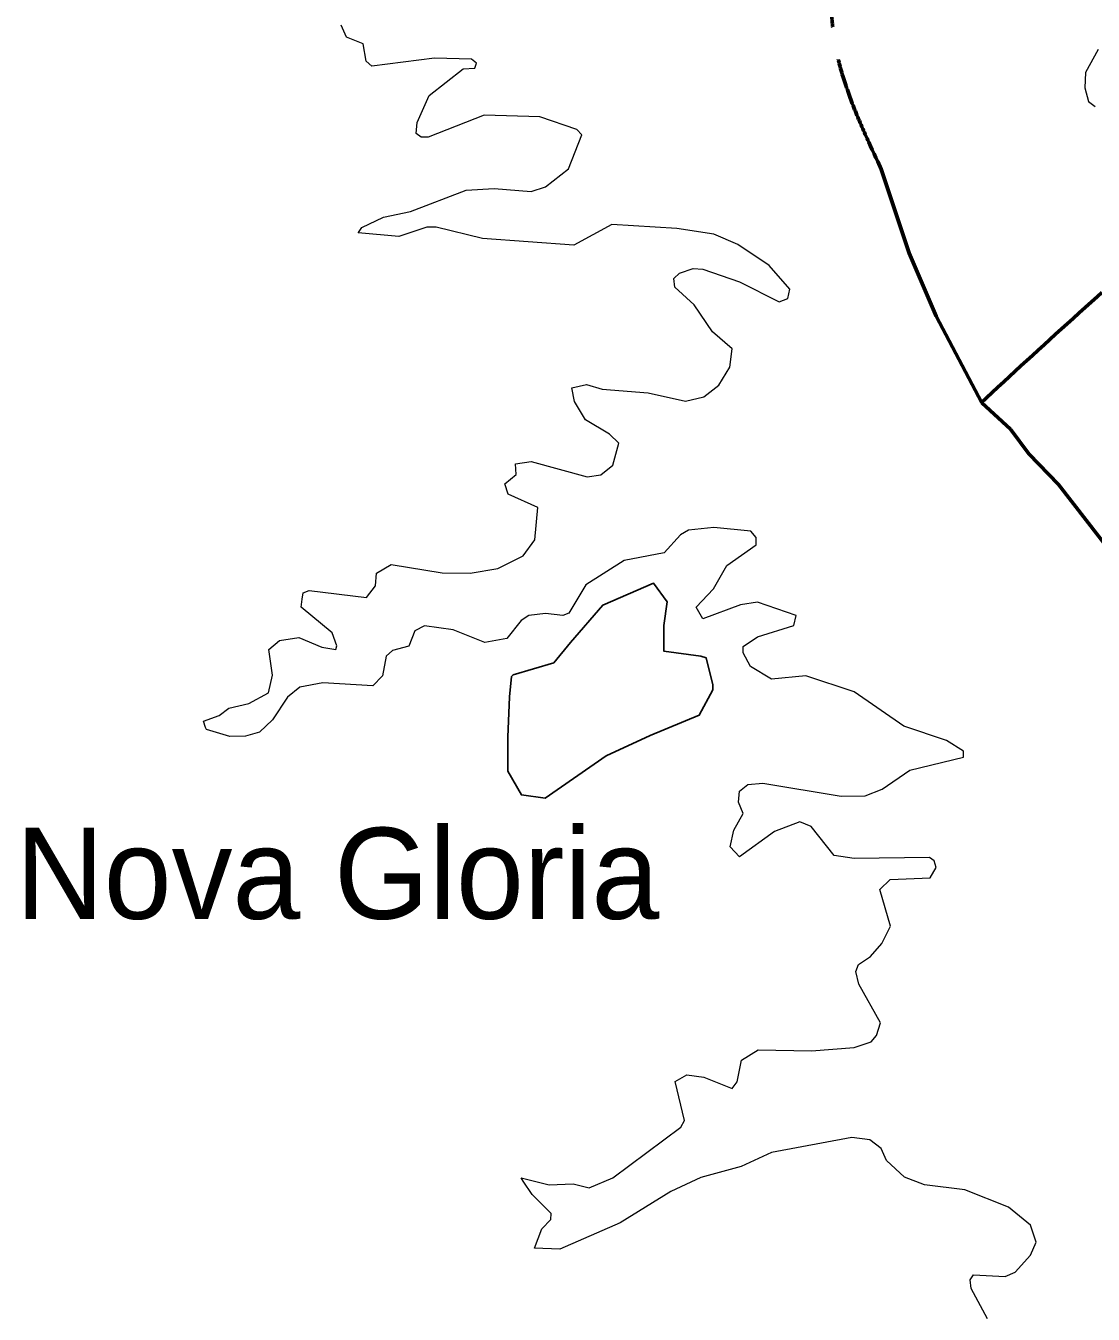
# Model space of a CAD drawing. Extents: x 553962 to 842807, y 8883888 to 9032388.
# Drawn here: x 578481 to 584337, y 8963682 to 8970754 of the extents above; entities that cross this region are included whole.
import ezdxf
from ezdxf.enums import TextEntityAlignment as Align

# ---------------------------------------------------------------- set-up
doc = ezdxf.new("R2010")
doc.units = 0
doc.header["$LTSCALE"] = 150
doc.linetypes.add('LONG_DASH_SHORT_DASH', pattern=[9.9, 6, -1.2, 1.5, -1.2])
for name, color, linetype, lineweight in [('21', 7, 'Continuous', 25), ('25', 7, 'Continuous', 13), ('7', 7, 'LONG_DASH_SHORT_DASH', 60)]:
    doc.layers.add(name, color=color, linetype=linetype, lineweight=lineweight)
doc.layers.add('41', color=7, linetype='Continuous')

msp = doc.modelspace()

# ---------------------------------------------------------------- linework, layer by layer
at = {"layer": '21'}
msp.add_lwpolyline([(581144.7, 8967182.6), (581135.4, 8967071.1), (581126.2, 8966848.2), (581126.2, 8966662.4), (581200.4, 8966532.3), (581330.4, 8966513.8), (581664.7, 8966746), (581906.1, 8966857.5), (582175.4, 8966968.9), (582249.7, 8967108.2), (582249.7, 8967136.1), (582212.6, 8967284.7), (582184.7, 8967294), (581980.4, 8967321.9), (581980.4, 8967461.2), (581999, 8967591.2), (581924.7, 8967693.4), (581646.1, 8967572.7), (581469.7, 8967368.3), (581376.9, 8967256.9), (581154, 8967191.8)], close=True, dxfattribs=at)
at = {"layer": '25'}
msp.add_line((579471.8, 8966890.6), (579467.6, 8966902.2), dxfattribs=at)
msp.add_line((579471.8, 8966890.6), (579467.6, 8966902.2), dxfattribs=at)
for points in [[(580309.7, 8969624.7), (580324.1, 8969646.6), (580442.8, 8969703), (580591, 8969734.8), (580897.4, 8969851.8), (581049.8, 8969860.2), (581253.8, 8969843.2), (581332.8, 8969868.9), (581457.9, 8969968.6), (581532.1, 8970155.4), (581503.8, 8970183.4), (581300.7, 8970253.2), (580995.1, 8970263.8), (580689.2, 8970142.9), (580650.8, 8970142.8), (580623.4, 8970161.8), (580627.3, 8970223.2), (580693.7, 8970370.5), (580880.2, 8970516.6), (580943.8, 8970521), (580954.3, 8970548.4), (580926, 8970569.8), (580722.7, 8970576.1), (580378.8, 8970531.6), (580349, 8970559.3), (580332.1, 8970654.5), (580240.8, 8970690.9), (580211.1, 8970756.7)], [(580309.7, 8969624.7), (580324.1, 8969646.6), (580442.8, 8969703), (580591, 8969734.8), (580897.4, 8969851.8), (581049.8, 8969860.2), (581253.8, 8969843.2), (581332.8, 8969868.9), (581457.9, 8969968.6), (581532.1, 8970155.4), (581503.8, 8970183.4), (581300.7, 8970253.2), (580995.1, 8970263.8), (580689.2, 8970142.9), (580650.8, 8970142.8), (580623.4, 8970161.8), (580627.3, 8970223.2), (580693.7, 8970370.5), (580880.2, 8970516.6), (580943.8, 8970521), (580954.3, 8970548.4), (580926, 8970569.8), (580722.7, 8970576.1), (580378.8, 8970531.6), (580349, 8970559.3), (580332.1, 8970654.5), (580240.8, 8970690.9), (580211.1, 8970756.7)], [(584364.7, 8970623), (584293.8, 8970497.2), (584291.7, 8970412.5), (584311, 8970338.1), (584347.1, 8970310.6)], [(584364.7, 8970623), (584293.8, 8970497.2), (584291.7, 8970412.5), (584311, 8970338.1), (584347.1, 8970310.6)], [(579997.9, 8967607), (580002.2, 8967641.4), (580036, 8967653.3), (580349.3, 8967615), (580399.9, 8967680.5), (580404.5, 8967748.8), (580485.3, 8967797.5), (580765.4, 8967750.9), (580918.4, 8967748.8), (581071.3, 8967774.2), (581209.4, 8967844.3), (581273.1, 8967931.4), (581290, 8968109.6), (581126.5, 8968182.3), (581109.5, 8968238.9), (581170.9, 8968290.2), (581167, 8968349.8), (581254, 8968362.6), (581560.2, 8968277.7), (581636.5, 8968288.5), (581702.2, 8968341.5), (581733.9, 8968462.6), (581683.1, 8968511.3), (581551.5, 8968590), (581492, 8968691.9), (581477.3, 8968766.3), (581557.6, 8968785.3), (581642.9, 8968759.5), (581895.5, 8968738.6), (582099.5, 8968694), (582201.4, 8968717.4), (582282.1, 8968781.1), (582343.8, 8968879.1), (582356.4, 8968980.7), (582248.2, 8969074.3), (582148.5, 8969222.7), (582042.2, 8969318.6), (582035.8, 8969367.1), (582067.6, 8969395), (582142, 8969420.5), (582195.2, 8969417.7), (582396.8, 8969348.3), (582613.7, 8969237.8), (582662.3, 8969257), (582672.9, 8969307.9), (582558.3, 8969437.5), (582387.3, 8969552.8), (582256.4, 8969609.6), (582053, 8969641.4), (581695.9, 8969662.6), (581486.8, 8969550.1), (580986.3, 8969586.2), (580731.4, 8969647.8), (580680.5, 8969647.7), (580527.5, 8969596.8), (580305.1, 8969617.7), (580309.7, 8969624.7)], [(579997.9, 8967607), (580002.2, 8967641.4), (580036, 8967653.3), (580349.3, 8967615), (580399.9, 8967680.5), (580404.5, 8967748.8), (580485.3, 8967797.5), (580765.4, 8967750.9), (580918.4, 8967748.8), (581071.3, 8967774.2), (581209.4, 8967844.3), (581273.1, 8967931.4), (581290, 8968109.6), (581126.5, 8968182.3), (581109.5, 8968238.9), (581170.9, 8968290.2), (581167, 8968349.8), (581254, 8968362.6), (581560.2, 8968277.7), (581636.5, 8968288.5), (581702.2, 8968341.5), (581733.9, 8968462.6), (581683.1, 8968511.3), (581551.5, 8968590), (581492, 8968691.9), (581477.3, 8968766.3), (581557.6, 8968785.3), (581642.9, 8968759.5), (581895.5, 8968738.6), (582099.5, 8968694), (582201.4, 8968717.4), (582282.1, 8968781.1), (582343.8, 8968879.1), (582356.4, 8968980.7), (582248.2, 8969074.3), (582148.5, 8969222.7), (582042.2, 8969318.6), (582035.8, 8969367.1), (582067.6, 8969395), (582142, 8969420.5), (582195.2, 8969417.7), (582396.8, 8969348.3), (582613.7, 8969237.8), (582662.3, 8969257), (582672.9, 8969307.9), (582558.3, 8969437.5), (582387.3, 8969552.8), (582256.4, 8969609.6), (582053, 8969641.4), (581695.9, 8969662.6), (581486.8, 8969550.1), (580986.3, 8969586.2), (580731.4, 8969647.8), (580680.5, 8969647.7), (580527.5, 8969596.8), (580305.1, 8969617.7), (580309.7, 8969624.7)], [(581209.9, 8964412.9), (581198.1, 8964430.9), (581351.7, 8964392.4), (581483.4, 8964396.6), (581572.4, 8964375.4), (581702.2, 8964430.7), (582073.9, 8964708.9), (582095.1, 8964745.1), (582044.3, 8964959.3), (582107.7, 8964995.5), (582107.7, 8964995.5), (582201.2, 8964983), (582356.2, 8964921.4), (582384.1, 8964957.7), (582407.6, 8965076.4), (582498.3, 8965133.6), (582792, 8965127.4), (583025.6, 8965146.5), (583119.2, 8965176.5), (583148.8, 8965212.4), (583170, 8965280.6), (583051.2, 8965492.5), (583034.2, 8965562.9), (583049.1, 8965601.1), (583114.8, 8965645.7), (583178, 8965717.2), (583225.2, 8965811.2), (583165.9, 8966013.2), (583223.5, 8966068.5), (583441.9, 8966077), (583475.9, 8966134.3), (583465.2, 8966170.4), (583439.6, 8966189.4), (583025.6, 8966183.2), (582915.7, 8966200), (582789.8, 8966359.4), (582728.2, 8966384.9), (582588.1, 8966331.8), (582396.7, 8966191.8), (582346, 8966247.1), (582364.9, 8966338), (582415.8, 8966429.6), (582390.2, 8966492.9), (582396.9, 8966552.7), (582441.5, 8966588.8), (582524.1, 8966597.4), (582953.4, 8966525.2), (583085.1, 8966527.3), (583178.8, 8966563.5), (583331.5, 8966667.5), (583624.5, 8966739.8), (583624.6, 8966771.3), (583531.2, 8966831), (583297.3, 8966909.8), (583025.6, 8967098.7), (582760.3, 8967185.7), (582571.1, 8967166.8), (582456.7, 8967236.5), (582416, 8967311.4), (582416.1, 8967347.1), (582494.8, 8967400.4), (582694, 8967461.9), (582706.9, 8967517.1), (582494.3, 8967589.4), (582401.1, 8967574.5), (582195.1, 8967498.2), (582159.1, 8967561.8), (582254.4, 8967663.6), (582326.8, 8967791.2), (582488.1, 8967904.1), (582488.1, 8967944.1), (582458.3, 8967980.2), (582256.4, 8967999.4), (582116.5, 8967984.5), (582071.9, 8967959), (581982.3, 8967861.3), (581763.8, 8967818.8), (581553.6, 8967684.9), (581459.8, 8967529.9), (581427.3, 8967517.2), (581332, 8967527.8), (581241.1, 8967517), (581198.8, 8967489.5), (581119.9, 8967389.7), (580998.9, 8967368.6), (580825.2, 8967438.5), (580667.5, 8967459.7), (580614.4, 8967431.8), (580582.4, 8967349.3), (580493.6, 8967323.8), (580457.7, 8967294.3), (580438.2, 8967185.8), (580385.3, 8967130.7), (580111.4, 8967147.6), (579983.5, 8967124), (579915.9, 8967069.1), (579835, 8966943.6), (579762.8, 8966875.7), (579686.3, 8966854.5), (579601.1, 8966852.3), (579471.8, 8966890.6)], [(581209.9, 8964412.9), (581198.1, 8964430.9), (581351.7, 8964392.4), (581483.4, 8964396.6), (581572.4, 8964375.4), (581702.2, 8964430.7), (582073.9, 8964708.9), (582095.1, 8964745.1), (582044.3, 8964959.3), (582107.7, 8964995.5), (582107.7, 8964995.5), (582201.2, 8964983), (582356.2, 8964921.4), (582384.1, 8964957.7), (582407.6, 8965076.4), (582498.3, 8965133.6), (582792, 8965127.4), (583025.6, 8965146.5), (583119.2, 8965176.5), (583148.8, 8965212.4), (583170, 8965280.6), (583051.2, 8965492.5), (583034.2, 8965562.9), (583049.1, 8965601.1), (583114.8, 8965645.7), (583178, 8965717.2), (583225.2, 8965811.2), (583165.9, 8966013.2), (583223.5, 8966068.5), (583441.9, 8966077), (583475.9, 8966134.3), (583465.2, 8966170.4), (583439.6, 8966189.4), (583025.6, 8966183.2), (582915.7, 8966200), (582789.8, 8966359.4), (582728.2, 8966384.9), (582588.1, 8966331.8), (582396.7, 8966191.8), (582346, 8966247.1), (582364.9, 8966338), (582415.8, 8966429.6), (582390.2, 8966492.9), (582396.9, 8966552.7), (582441.5, 8966588.8), (582524.1, 8966597.4), (582953.4, 8966525.2), (583085.1, 8966527.3), (583178.8, 8966563.5), (583331.5, 8966667.5), (583624.5, 8966739.8), (583624.6, 8966771.3), (583531.2, 8966831), (583297.3, 8966909.8), (583025.6, 8967098.7), (582760.3, 8967185.7), (582571.1, 8967166.8), (582456.7, 8967236.5), (582416, 8967311.4), (582416.1, 8967347.1), (582494.8, 8967400.4), (582694, 8967461.9), (582706.9, 8967517.1), (582494.3, 8967589.4), (582401.1, 8967574.5), (582195.1, 8967498.2), (582159.1, 8967561.8), (582254.4, 8967663.6), (582326.8, 8967791.2), (582488.1, 8967904.1), (582488.1, 8967944.1), (582458.3, 8967980.2), (582256.4, 8967999.4), (582116.5, 8967984.5), (582071.9, 8967959), (581982.3, 8967861.3), (581763.8, 8967818.8), (581553.6, 8967684.9), (581459.8, 8967529.9), (581427.3, 8967517.2), (581332, 8967527.8), (581241.1, 8967517), (581198.8, 8967489.5), (581119.9, 8967389.7), (580998.9, 8967368.6), (580825.2, 8967438.5), (580667.5, 8967459.7), (580614.4, 8967431.8), (580582.4, 8967349.3), (580493.6, 8967323.8), (580457.7, 8967294.3), (580438.2, 8967185.8), (580385.3, 8967130.7), (580111.4, 8967147.6), (579983.5, 8967124), (579915.9, 8967069.1), (579835, 8966943.6), (579762.8, 8966875.7), (579686.3, 8966854.5), (579601.1, 8966852.3), (579471.8, 8966890.6)], [(579467.6, 8966902.2), (579455.3, 8966936.2), (579541.6, 8966967.5), (579595, 8967007.3), (579704, 8967033.2), (579811.7, 8967092.6), (579835, 8967188.5), (579813.9, 8967330.2), (579873.1, 8967378.9), (579979.2, 8967396.1), (580105, 8967343), (580105, 8967343), (580181.1, 8967330.4), (580187.4, 8967349.7), (580161, 8967421.7), (579992.3, 8967561.8), (579997.9, 8967607)], [(579467.6, 8966902.2), (579455.3, 8966936.2), (579541.6, 8966967.5), (579595, 8967007.3), (579704, 8967033.2), (579811.7, 8967092.6), (579835, 8967188.5), (579813.9, 8967330.2), (579873.1, 8967378.9), (579979.2, 8967396.1), (580105, 8967343), (580105, 8967343), (580181.1, 8967330.4), (580187.4, 8967349.7), (580161, 8967421.7), (579992.3, 8967561.8), (579997.9, 8967607)], [(583013.2, 8964651.5), (582571.3, 8964568.8), (582405.6, 8964492.4), (582184.7, 8964432.8), (582018.8, 8964356.3), (581742.6, 8964184.2), (581411.2, 8964039.8), (581271.6, 8964044.5), (581311.5, 8964150.2), (581362.2, 8964201), (581362.3, 8964235), (581258.4, 8964339.1), (581209.9, 8964412.9)], [(583013.2, 8964651.5), (582571.3, 8964568.8), (582405.6, 8964492.4), (582184.7, 8964432.8), (582018.8, 8964356.3), (581742.6, 8964184.2), (581411.2, 8964039.8), (581271.6, 8964044.5), (581311.5, 8964150.2), (581362.2, 8964201), (581362.3, 8964235), (581258.4, 8964339.1), (581209.9, 8964412.9)], [(583756.3, 8963657.4), (583667.3, 8963822.9), (583661, 8963870), (583680, 8963897.4), (583854.1, 8963889), (583909.5, 8963912.6), (583992, 8964005.7), (584023.8, 8964077.5), (583992.3, 8964171.2), (583871.3, 8964269), (583632.9, 8964364.8), (583412.2, 8964392.4), (583302.1, 8964434.8), (583202.2, 8964526), (583174.1, 8964592.2), (583110.6, 8964638.7), (583013.2, 8964651.5)], [(583756.3, 8963657.4), (583667.3, 8963822.9), (583661, 8963870), (583680, 8963897.4), (583854.1, 8963889), (583909.5, 8963912.6), (583992, 8964005.7), (584023.8, 8964077.5), (583992.3, 8964171.2), (583871.3, 8964269), (583632.9, 8964364.8), (583412.2, 8964392.4), (583302.1, 8964434.8), (583202.2, 8964526), (583174.1, 8964592.2), (583110.6, 8964638.7), (583013.2, 8964651.5)]]:
    msp.add_lwpolyline(points, dxfattribs=at)
at = {"layer": '7'}
msp.add_lwpolyline([(583174.4, 8969966), (583327.9, 8969505.4), (583474.7, 8969160.4), (583725.5, 8968684.8), (583883.2, 8968539.9), (583982.9, 8968403.5), (584146.9, 8968235.1), (584624.8, 8967616.6), (584992.2, 8967072.1), (585186.8, 8966825.7), (585377.2, 8966655.9), (585748.8, 8966438.6), (585960.5, 8966257.3), (586351.6, 8965976.8), (586551, 8965796.4), (587006.6, 8965310.9), (587303.1, 8964815.2), (587426.7, 8964495.3)], dxfattribs=at)
for points in [[(581705.4, 8974333.7), (582461.9, 8973819.1), (583080, 8973133.9), (583131.7, 8972182.4), (582921.5, 8970648.2), (583174.4, 8969966)], [(583719.8, 8968683.1), (584226, 8969147.1), (585263.8, 8970159.6), (585803.8, 8970817.7), (586453.4, 8971391.4), (587077.8, 8971939.8), (587744.3, 8972277.3), (588469.9, 8972403.9), (588728.8, 8972391.8)]]:
    msp.add_spline(points, degree=3, dxfattribs=at)

# ---------------------------------------------------------------- texts
at = {"layer": '41'}
msp.add_text('Nova Gloria', height=500, dxfattribs=at).set_placement((580191.1, 8965851.8), align=Align.CENTER)

doc.saveas('drawing.dxf')
